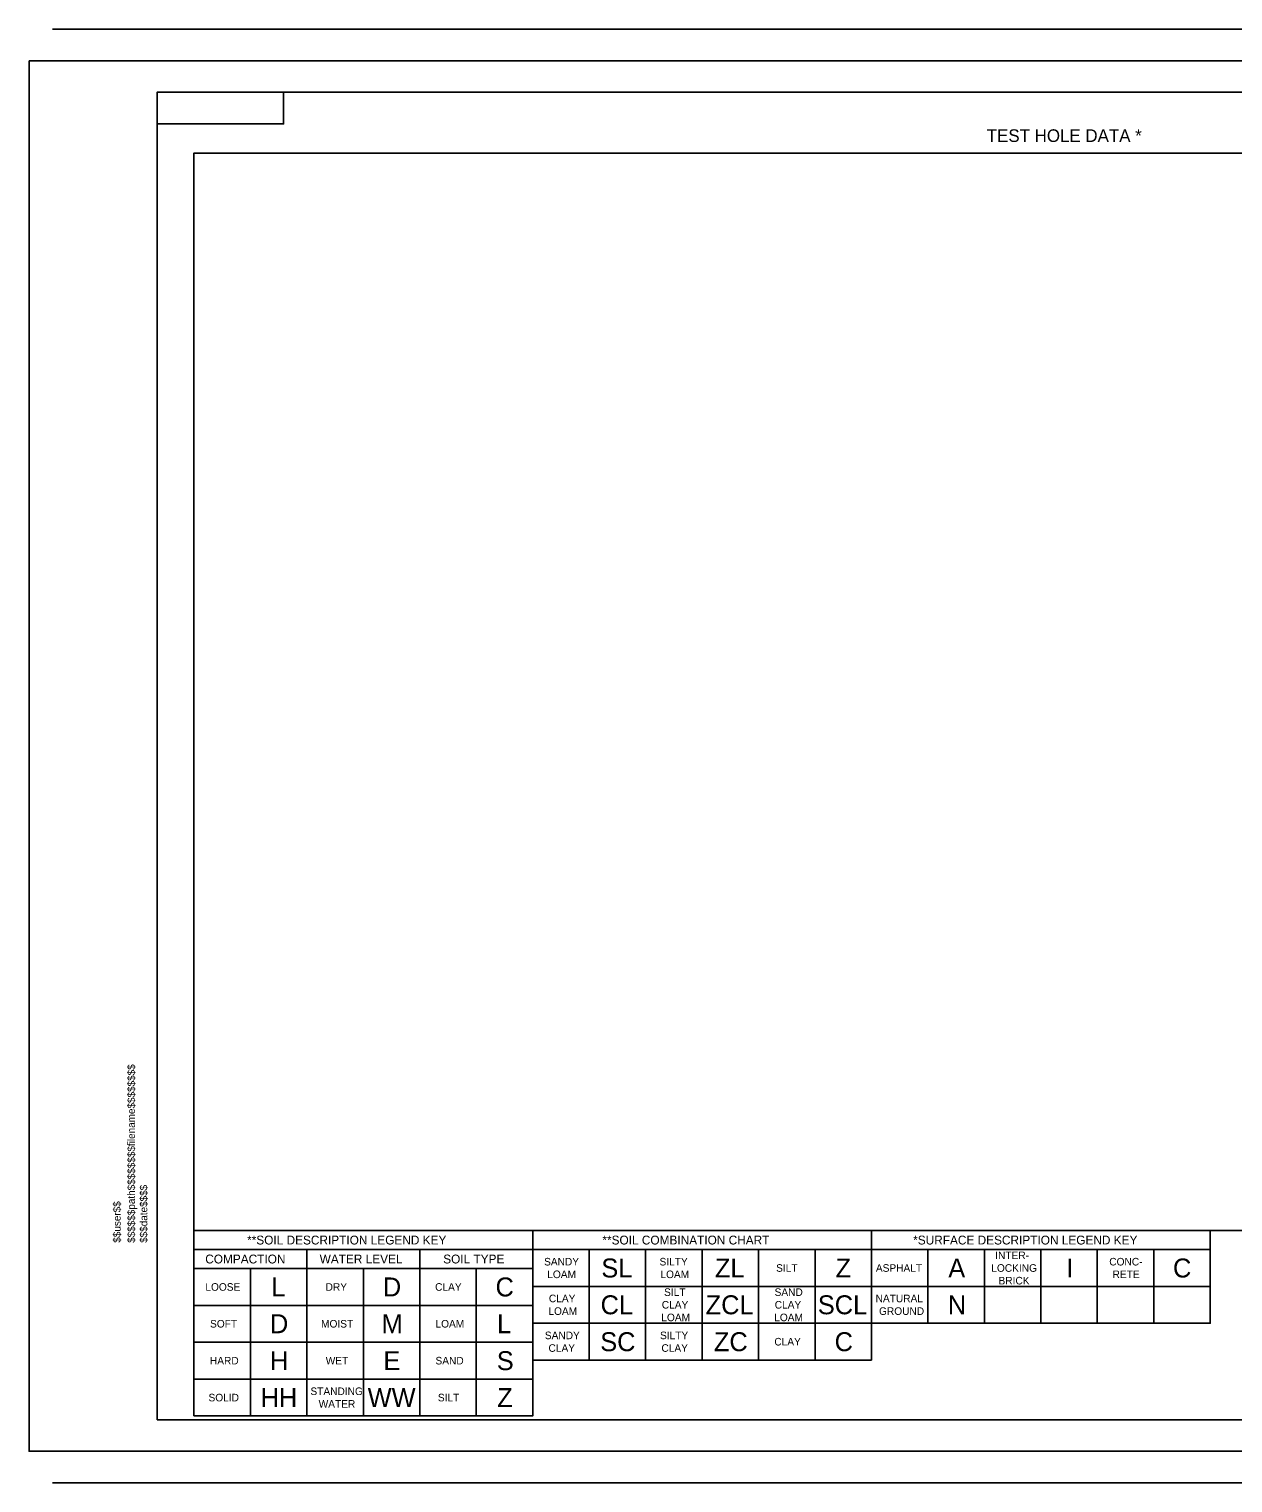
# Model space of a CAD drawing. Extents: x 12327 to 14123, y 15818 to 16968.
# Drawn here: x 12327 to 13279, y 15818 to 16968 of the extents above; entities that cross this region are included whole.
import ezdxf

# ---------------------------------------------------------------- set-up
doc = ezdxf.new("R2010")
doc.units = 0
for name, color, linetype in [('GN_Transparent 20', 7, 'Continuous'), ('RD_SHT_Bndy', 7, 'Continuous'), ('RD_SHT_ID', 7, 'Continuous'), ('RD_SHT_Iplotshp', 7, 'Continuous'), ('RD_SHT_Snap', 7, 'Continuous'), ('RD_SHT_TX', 7, 'Continuous')]:
    doc.layers.add(name, color=color, linetype=linetype)

msp = doc.modelspace()

# ---------------------------------------------------------------- linework, layer by layer
at = {"layer": 'GN_Transparent 20'}
msp.add_lwpolyline([(12457.7, 16018), (14071.7, 16018), (14071.7, 16870.3), (12457.7, 16870.3)], close=True, dxfattribs=at)
at = {"layer": 'RD_SHT_Bndy'}
for p, q in [((14105.9, 16968.4), (12345.9, 16968.4)), ((14105.9, 16943.4), (12345.9, 16943.4)), ((14103.5, 16918.4), (12428.5, 16918.4)), ((12428.5, 16918.4), (12428.5, 15868.4)), ((12428.5, 16018.4), (12428.5, 15868.4)), ((12428.5, 15868.4), (14103.5, 15868.4)), ((14105.9, 15843.4), (12345.9, 15843.4)), ((14105.9, 15818.4), (12345.9, 15818.4))]:
    msp.add_line(p, q, dxfattribs=at)
for points in [[(12428.5, 16893.4), (12428.5, 16918.4), (12528.5, 16918.4), (12528.5, 16893.4)], [(12457.7, 16003), (12725.6, 16003), (12725.6, 16018), (12457.7, 16018)], [(12725.6, 16003), (12993.5, 16003), (12993.5, 16018), (12725.6, 16018)], [(12993.5, 16003), (13261.4, 16003), (13261.4, 16018), (12993.5, 16018)], [(12457.7, 15988), (12547, 15988), (12547, 16003), (12457.7, 16003)], [(12547, 15988), (12636.3, 15988), (12636.3, 16003), (12547, 16003)], [(12636.3, 15988), (12725.6, 15988), (12725.6, 16003), (12636.3, 16003)], [(12725.6, 15973.8), (12770.3, 15973.8), (12770.3, 16003), (12725.6, 16003)], [(12770.3, 15973.8), (12814.9, 15973.8), (12814.9, 16003), (12770.3, 16003)], [(12814.9, 15973.8), (12859.6, 15973.8), (12859.6, 16003), (12814.9, 16003)], [(12904.2, 15973.8), (12948.9, 15973.8), (12948.9, 16003), (12904.2, 16003)], [(12948.9, 15973.8), (12993.5, 15973.8), (12993.5, 16003), (12948.9, 16003)], [(12993.5, 15973.8), (13038.2, 15973.8), (13038.2, 16003), (12993.5, 16003)], [(13038.2, 15973.8), (13082.8, 15973.8), (13082.8, 16003), (13038.2, 16003)], [(13082.8, 15973.8), (13127.5, 15973.8), (13127.5, 16003), (13082.8, 16003)], [(13127.5, 15973.8), (13172.1, 15973.8), (13172.1, 16003), (13127.5, 16003)], [(13172.1, 15973.8), (13216.8, 15973.8), (13216.8, 16003), (13172.1, 16003)], [(13216.8, 15973.8), (13261.4, 15973.8), (13261.4, 16003), (13216.8, 16003)], [(12457.7, 15958.8), (12502.4, 15958.8), (12502.4, 15988), (12457.7, 15988)], [(12502.4, 15958.8), (12547, 15958.8), (12547, 15988), (12502.4, 15988)], [(12547, 15958.8), (12591.7, 15958.8), (12591.7, 15988), (12547, 15988)], [(12591.7, 15958.8), (12636.3, 15958.8), (12636.3, 15988), (12591.7, 15988)], [(12636.3, 15958.8), (12681, 15958.8), (12681, 15988), (12636.3, 15988)], [(12681, 15958.8), (12725.6, 15958.8), (12725.6, 15988), (12681, 15988)], [(12725.6, 15944.7), (12770.3, 15944.7), (12770.3, 15973.8), (12725.6, 15973.8)], [(12770.3, 15944.7), (12814.9, 15944.7), (12814.9, 15973.8), (12770.3, 15973.8)], [(12814.9, 15944.7), (12859.6, 15944.7), (12859.6, 15973.8), (12814.9, 15973.8)], [(12859.6, 15944.7), (12904.2, 15944.7), (12904.2, 15973.8), (12859.6, 15973.8)], [(12904.2, 15944.7), (12948.9, 15944.7), (12948.9, 15973.8), (12904.2, 15973.8)], [(12948.9, 15944.7), (12993.5, 15944.7), (12993.5, 15973.8), (12948.9, 15973.8)], [(12993.5, 15944.7), (13038.2, 15944.7), (13038.2, 15973.8), (12993.5, 15973.8)], [(13038.2, 15944.7), (13082.8, 15944.7), (13082.8, 15973.8), (13038.2, 15973.8)], [(13082.8, 15944.7), (13127.5, 15944.7), (13127.5, 15973.8), (13082.8, 15973.8)], [(13127.5, 15944.7), (13172.1, 15944.7), (13172.1, 15973.8), (13127.5, 15973.8)], [(13172.1, 15944.7), (13216.8, 15944.7), (13216.8, 15973.8), (13172.1, 15973.8)], [(13216.8, 15944.7), (13261.4, 15944.7), (13261.4, 15973.8), (13216.8, 15973.8)], [(12457.7, 15929.7), (12502.4, 15929.7), (12502.4, 15958.8), (12457.7, 15958.8)], [(12502.4, 15929.7), (12547, 15929.7), (12547, 15958.8), (12502.4, 15958.8)], [(12547, 15929.7), (12591.7, 15929.7), (12591.7, 15958.8), (12547, 15958.8)], [(12591.7, 15929.7), (12636.3, 15929.7), (12636.3, 15958.8), (12591.7, 15958.8)], [(12636.3, 15929.7), (12681, 15929.7), (12681, 15958.8), (12636.3, 15958.8)], [(12681, 15929.7), (12725.6, 15929.7), (12725.6, 15958.8), (12681, 15958.8)], [(12725.6, 15915.5), (12770.3, 15915.5), (12770.3, 15944.7), (12725.6, 15944.7)], [(12770.3, 15915.5), (12814.9, 15915.5), (12814.9, 15944.7), (12770.3, 15944.7)], [(12814.9, 15915.5), (12859.6, 15915.5), (12859.6, 15944.7), (12814.9, 15944.7)], [(12859.6, 15915.5), (12904.2, 15915.5), (12904.2, 15944.7), (12859.6, 15944.7)], [(12904.2, 15915.5), (12948.9, 15915.5), (12948.9, 15944.7), (12904.2, 15944.7)], [(12948.9, 15915.5), (12993.5, 15915.5), (12993.5, 15944.7), (12948.9, 15944.7)], [(12457.7, 15900.5), (12502.4, 15900.5), (12502.4, 15929.7), (12457.7, 15929.7)], [(12502.4, 15900.5), (12547, 15900.5), (12547, 15929.7), (12502.4, 15929.7)], [(12547, 15900.5), (12591.7, 15900.5), (12591.7, 15929.7), (12547, 15929.7)], [(12591.7, 15900.5), (12636.3, 15900.5), (12636.3, 15929.7), (12591.7, 15929.7)], [(12636.3, 15900.5), (12681, 15900.5), (12681, 15929.7), (12636.3, 15929.7)], [(12681, 15900.5), (12725.6, 15900.5), (12725.6, 15929.7), (12681, 15929.7)], [(12457.7, 15871.4), (12502.4, 15871.4), (12502.4, 15900.5), (12457.7, 15900.5)], [(12502.4, 15871.4), (12547, 15871.4), (12547, 15900.5), (12502.4, 15900.5)], [(12547, 15871.4), (12591.7, 15871.4), (12591.7, 15900.5), (12547, 15900.5)], [(12591.7, 15871.4), (12636.3, 15871.4), (12636.3, 15900.5), (12591.7, 15900.5)], [(12636.3, 15871.4), (12681, 15871.4), (12681, 15900.5), (12636.3, 15900.5)], [(12681, 15871.4), (12725.6, 15871.4), (12725.6, 15900.5), (12681, 15900.5)]]:
    msp.add_lwpolyline(points, close=True, dxfattribs=at)
at = {"layer": 'RD_SHT_Iplotshp'}
msp.add_lwpolyline([(12327.3, 16943.4), (14123.3, 16943.4), (14123.3, 15843.4), (12327.3, 15843.4)], close=True, dxfattribs=at)
at = {"layer": 'RD_SHT_Snap'}
msp.add_line((12327.3, 15843.4), (12327.3, 16943.4), dxfattribs=at)
at = {"layer": 'RD_SHT_TX'}
msp.add_lwpolyline([(12859.6, 15973.8), (12904.2, 15973.8), (12904.2, 16003), (12859.6, 16003)], close=True, dxfattribs=at)

# ---------------------------------------------------------------- texts
at = {"layer": 'RD_SHT_ID'}
for s, p in [('$$$$$$path$$$$$$$$filename$$$$$$$$', (12411, 16008.3)), ('$$$date$$$$', (12420.8, 16008.3)), ('$$user$$', (12399.7, 16008.4))]:
    msp.add_text(s, height=5.88, rotation=90, dxfattribs=at).set_placement(p)
at = {"layer": 'RD_SHT_TX'}
for s, height, p in [('TEST HOLE DATA *', 10, (13084.7, 16879.1)), ('SANDY', 6, (12734.6, 15990.4)), ('SILTY', 6, (12825.9, 15990.4)), ('INTER-', 6, (13091.4, 15995.4)), ('CONC-', 6, (13181.6, 15990.4)), ('LOAM', 6, (12737.1, 15980.4)), ('SL', 15, (12779.9, 15980.9)), ('LOAM', 6, (12826.6, 15980.4)), ('ZL', 15, (12869.7, 15980.9)), ('SILT', 6, (12918.1, 15985.4)), ('Z', 15, (12965.1, 15980.9)), ('ASPHALT', 6, (12997, 15985.4)), ('A', 15, (13054.3, 15980.9)), ('LOCKING', 6, (13088.3, 15985.4)), ('I', 15, (13147.7, 15980.9)), ('RETE', 6, (13184.2, 15980.4)), ('C', 15, (13232, 15980.9)), ('LOOSE', 6, (12466.7, 15970.4)), ('L', 15, (12518.8, 15965.9)), ('DRY', 6, (12561.8, 15970.4)), ('D', 15, (12607.1, 15965.9)), ('CLAY', 6, (12648.4, 15970.4)), ('C', 15, (12696.2, 15965.9)), ('BRICK', 6, (13094, 15975.4)), ('CLAY', 6, (12738.4, 15961.3)), ('CL', 15, (12779.3, 15951.8)), ('CLAY', 6, (12827.7, 15956.3)), ('SILT', 6, (12829.5, 15966.3)), ('ZCL', 15, (12862.4, 15951.8)), ('SAND', 6, (12916.9, 15966.3)), ('CLAY', 6, (12917, 15956.3)), ('SCL', 15, (12951.1, 15951.8)), ('NATURAL', 6, (12996.8, 15961.3)), ('N', 15, (13053.9, 15951.8)), ('D', 15, (12517.8, 15936.8)), ('M', 15, (12606.1, 15936.8)), ('L', 15, (12697.4, 15936.8)), ('LOAM', 6, (12738, 15951.3)), ('LOAM', 6, (12827.3, 15946.3)), ('LOAM', 6, (12916.6, 15946.3)), ('GROUND', 6, (12999.5, 15951.3)), ('SOFT', 6, (12470.4, 15941.3)), ('MOIST', 6, (12558.2, 15941.3)), ('LOAM', 6, (12648.7, 15941.3)), ('SANDY', 6, (12735.2, 15932.1)), ('CLAY', 6, (12738.1, 15922.1)), ('SC', 15, (12779, 15922.6)), ('SILTY', 6, (12826.3, 15932.1)), ('CLAY', 6, (12827.4, 15922.1)), ('ZC', 15, (12868.9, 15922.6)), ('CLAY', 6, (12916.7, 15927.1)), ('C', 15, (12964.4, 15922.6)), ('HARD', 6, (12470.3, 15912.1)), ('H', 15, (12517.8, 15907.6)), ('WET', 6, (12561.9, 15912.1)), ('E', 15, (12607.5, 15907.6)), ('SAND', 6, (12648.7, 15912.1)), ('S', 15, (12697.2, 15907.6)), ('HH', 15, (12510.4, 15878.4)), ('STANDING', 6, (12549.8, 15887.9)), ('WW', 15, (12595.1, 15878.4)), ('Z', 15, (12697.5, 15878.4)), ('SOLID', 6, (12469.2, 15882.9)), ('WATER', 6, (12556.3, 15877.9)), ('SILT', 6, (12650.6, 15882.9))]:
    msp.add_text(s, height=height, dxfattribs=at).set_placement(p)
for s, p in [('**SOIL DESCRIPTION LEGEND KEY', (12499.7, 16007)), ('**SOIL COMBINATION CHART', (12780.7, 16007)), ('*SURFACE DESCRIPTION LEGEND KEY', (13026.5, 16007)), ('COMPACTION', (12466.6, 15992)), ('WATER LEVEL', (12557.1, 15992)), ('SOIL TYPE', (12654.8, 15992))]:
    msp.add_text(s, height=7, rotation=360, dxfattribs=at).set_placement(p)

doc.saveas('drawing.dxf')
